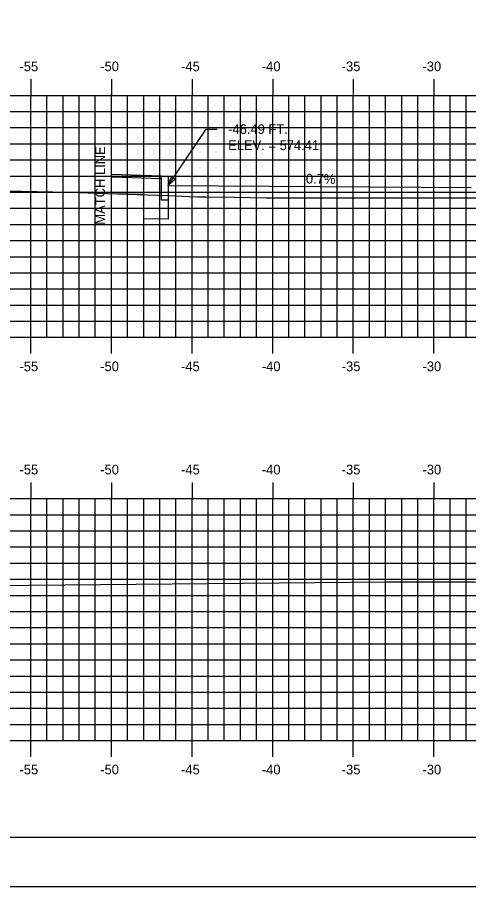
# Model space of a CAD drawing. Extents: x 1048109 to 1048279, y 781630 to 781740.
# Drawn here: x 1048135.9 to 1048163.9, y 781630.1 to 781684 of the extents above; entities that cross this region are included whole.
import ezdxf

# ---------------------------------------------------------------- set-up
doc = ezdxf.new("R2010")
doc.units = 0
for name, color, linetype in [('ANNOTATION', 7, 'Continuous'), ('D_Curb_Type1_Lt', 7, 'Continuous'), ('D_Roadway_Centerline', 7, 'Continuous'), ('D_Roadway_SubGrade', 7, 'Continuous'), ('D_Text_Standard', 7, 'Continuous'), ('Default', 7, 'Continuous'), ('E_ROW_Line', 7, 'Continuous'), ('H_V ANNOTATION', 7, 'Continuous'), ('MAJOR', 7, 'Continuous'), ('MINOR', 7, 'Continuous'), ('S_Roadway_Centerline', 7, 'Continuous'), ('S_Roadway_Edge_Pavement', 7, 'Continuous')]:
    doc.layers.add(name, color=color, linetype=linetype)

msp = doc.modelspace()

# ---------------------------------------------------------------- linework, layer by layer
at = {"layer": 'D_Curb_Type1_Lt'}
msp.add_lwpolyline([(1048145.246, 781674.189), (1048145.246, 781672.689), (1048144.829, 781672.689), (1048144.829, 781674.189)], close=True, dxfattribs=at)
at = {"layer": 'D_Roadway_Centerline'}
msp.add_line((1048145.246, 781673.605), (1048164.033, 781673.476), dxfattribs=at)
at = {"layer": 'D_Roadway_SubGrade'}
for p, q in [((1048144.829, 781674.189), (1048141.733, 781674.292)), ((1048144.829, 781674.022), (1048141.733, 781674.125)), ((1048145.246, 781673.605), (1048145.246, 781671.522)), ((1048145.246, 781671.522), (1048143.746, 781671.552))]:
    msp.add_line(p, q, dxfattribs=at)
msp.add_lwpolyline([(1048143.746, 781671.552), (1048143.746, 781673.053), (1048141.733, 781673.093)], dxfattribs=at)
at = {"layer": 'D_Text_Standard'}
msp.add_lwpolyline([(1048145.246, 781673.605), (1048147.612, 781677.105), (1048148.292, 781677.105)], dxfattribs=at)
msp.add_lwpolyline([(1048145.246, 781673.605), (1048145.451, 781674.169), (1048145.693, 781674.006)], close=True, dxfattribs=at)
at = {"layer": 'Default'}
msp.add_line((1048116.734, 781633.195), (1048276.734, 781633.195), dxfattribs=at)
msp.add_lwpolyline([(1048108.64, 781630.136), (1048278.64, 781630.136), (1048278.64, 781740.136), (1048108.64, 781740.136)], close=True, dxfattribs=at)
at = {"layer": 'E_ROW_Line'}
msp.add_line((1048141.733, 781669.251), (1048141.733, 781679.251), dxfattribs=at)
at = {"layer": 'MAJOR'}
for p, q in [((1048136.733, 781680.197), (1048136.733, 781679.195)), ((1048136.733, 781680.197), (1048136.733, 781679.195)), ((1048141.733, 781680.197), (1048141.733, 781679.195)), ((1048141.733, 781680.197), (1048141.733, 781679.195)), ((1048146.733, 781680.197), (1048146.733, 781679.195)), ((1048146.733, 781680.197), (1048146.733, 781679.195)), ((1048151.733, 781680.197), (1048151.733, 781679.195)), ((1048151.733, 781680.197), (1048151.733, 781679.195)), ((1048156.733, 781680.197), (1048156.733, 781679.195)), ((1048156.733, 781680.197), (1048156.733, 781679.195)), ((1048161.733, 781680.197), (1048161.733, 781679.195)), ((1048161.733, 781680.197), (1048161.733, 781679.195)), ((1048121.733, 781679.195), (1048261.733, 781679.195)), ((1048121.733, 781679.195), (1048261.733, 781679.195)), ((1048121.733, 781679.195), (1048261.733, 781679.195)), ((1048121.733, 781679.195), (1048261.733, 781679.195)), ((1048136.733, 781664.195), (1048136.733, 781679.195)), ((1048136.733, 781664.195), (1048136.733, 781679.195)), ((1048141.733, 781664.195), (1048141.733, 781679.195)), ((1048141.733, 781664.195), (1048141.733, 781679.195)), ((1048146.733, 781664.195), (1048146.733, 781679.195)), ((1048146.733, 781664.195), (1048146.733, 781679.195)), ((1048151.733, 781664.195), (1048151.733, 781679.195)), ((1048151.733, 781664.195), (1048151.733, 781679.195)), ((1048156.733, 781664.195), (1048156.733, 781679.195)), ((1048156.733, 781664.195), (1048156.733, 781679.195)), ((1048161.733, 781664.195), (1048161.733, 781679.195)), ((1048161.733, 781664.195), (1048161.733, 781679.195)), ((1048121.733, 781674.195), (1048261.733, 781674.195)), ((1048121.733, 781674.195), (1048261.733, 781674.195)), ((1048121.733, 781669.195), (1048261.733, 781669.195)), ((1048121.733, 781669.195), (1048261.733, 781669.195)), ((1048121.733, 781664.195), (1048261.733, 781664.195)), ((1048121.733, 781664.195), (1048261.733, 781664.195)), ((1048121.733, 781664.195), (1048261.733, 781664.195)), ((1048121.733, 781664.195), (1048261.733, 781664.195)), ((1048136.733, 781663.193), (1048136.733, 781664.195)), ((1048136.733, 781663.193), (1048136.733, 781664.195)), ((1048141.733, 781663.193), (1048141.733, 781664.195)), ((1048141.733, 781663.193), (1048141.733, 781664.195)), ((1048146.733, 781663.193), (1048146.733, 781664.195)), ((1048146.733, 781663.193), (1048146.733, 781664.195)), ((1048151.733, 781663.193), (1048151.733, 781664.195)), ((1048151.733, 781663.193), (1048151.733, 781664.195)), ((1048156.733, 781663.193), (1048156.733, 781664.195)), ((1048156.733, 781663.193), (1048156.733, 781664.195)), ((1048161.733, 781663.193), (1048161.733, 781664.195)), ((1048161.733, 781663.193), (1048161.733, 781664.195)), ((1048136.733, 781655.197), (1048136.733, 781654.195)), ((1048136.733, 781655.197), (1048136.733, 781654.195)), ((1048141.733, 781655.197), (1048141.733, 781654.195)), ((1048141.733, 781655.197), (1048141.733, 781654.195)), ((1048146.733, 781655.197), (1048146.733, 781654.195)), ((1048146.733, 781655.197), (1048146.733, 781654.195)), ((1048151.733, 781655.197), (1048151.733, 781654.195)), ((1048151.733, 781655.197), (1048151.733, 781654.195)), ((1048156.733, 781655.197), (1048156.733, 781654.195)), ((1048156.733, 781655.197), (1048156.733, 781654.195)), ((1048161.733, 781655.197), (1048161.733, 781654.195)), ((1048161.733, 781655.197), (1048161.733, 781654.195)), ((1048121.733, 781654.195), (1048261.733, 781654.195)), ((1048121.733, 781654.195), (1048261.733, 781654.195)), ((1048121.733, 781654.195), (1048261.733, 781654.195)), ((1048121.733, 781654.195), (1048261.733, 781654.195)), ((1048136.733, 781639.195), (1048136.733, 781654.195)), ((1048136.733, 781639.195), (1048136.733, 781654.195)), ((1048141.733, 781639.195), (1048141.733, 781654.195)), ((1048141.733, 781639.195), (1048141.733, 781654.195)), ((1048146.733, 781639.195), (1048146.733, 781654.195)), ((1048146.733, 781639.195), (1048146.733, 781654.195)), ((1048151.733, 781639.195), (1048151.733, 781654.195)), ((1048151.733, 781639.195), (1048151.733, 781654.195)), ((1048156.733, 781639.195), (1048156.733, 781654.195)), ((1048156.733, 781639.195), (1048156.733, 781654.195)), ((1048161.733, 781639.195), (1048161.733, 781654.195)), ((1048161.733, 781639.195), (1048161.733, 781654.195)), ((1048121.733, 781649.195), (1048261.733, 781649.195)), ((1048121.733, 781649.195), (1048261.733, 781649.195)), ((1048121.733, 781644.195), (1048261.733, 781644.195)), ((1048121.733, 781644.195), (1048261.733, 781644.195)), ((1048121.733, 781639.195), (1048261.733, 781639.195)), ((1048121.733, 781639.195), (1048261.733, 781639.195)), ((1048121.733, 781639.195), (1048261.733, 781639.195)), ((1048121.733, 781639.195), (1048261.733, 781639.195)), ((1048136.733, 781638.193), (1048136.733, 781639.195)), ((1048136.733, 781638.193), (1048136.733, 781639.195)), ((1048141.733, 781638.193), (1048141.733, 781639.195)), ((1048141.733, 781638.193), (1048141.733, 781639.195)), ((1048146.733, 781638.193), (1048146.733, 781639.195)), ((1048146.733, 781638.193), (1048146.733, 781639.195)), ((1048151.733, 781638.193), (1048151.733, 781639.195)), ((1048151.733, 781638.193), (1048151.733, 781639.195)), ((1048156.733, 781638.193), (1048156.733, 781639.195)), ((1048156.733, 781638.193), (1048156.733, 781639.195)), ((1048161.733, 781638.193), (1048161.733, 781639.195)), ((1048161.733, 781638.193), (1048161.733, 781639.195))]:
    msp.add_line(p, q, dxfattribs=at)
at = {"layer": 'MINOR'}
for p, q in [((1048137.733, 781664.195), (1048137.733, 781679.195)), ((1048137.733, 781664.195), (1048137.733, 781679.195)), ((1048138.733, 781664.195), (1048138.733, 781679.195)), ((1048138.733, 781664.195), (1048138.733, 781679.195)), ((1048139.733, 781664.195), (1048139.733, 781679.195)), ((1048139.733, 781664.195), (1048139.733, 781679.195)), ((1048140.733, 781664.195), (1048140.733, 781679.195)), ((1048140.733, 781664.195), (1048140.733, 781679.195)), ((1048142.733, 781664.195), (1048142.733, 781679.195)), ((1048142.733, 781664.195), (1048142.733, 781679.195)), ((1048143.733, 781664.195), (1048143.733, 781679.195)), ((1048143.733, 781664.195), (1048143.733, 781679.195)), ((1048144.733, 781664.195), (1048144.733, 781679.195)), ((1048144.733, 781664.195), (1048144.733, 781679.195)), ((1048145.733, 781664.195), (1048145.733, 781679.195)), ((1048145.733, 781664.195), (1048145.733, 781679.195)), ((1048147.733, 781664.195), (1048147.733, 781679.195)), ((1048147.733, 781664.195), (1048147.733, 781679.195)), ((1048148.733, 781664.195), (1048148.733, 781679.195)), ((1048148.733, 781664.195), (1048148.733, 781679.195)), ((1048149.733, 781664.195), (1048149.733, 781679.195)), ((1048149.733, 781664.195), (1048149.733, 781679.195)), ((1048150.733, 781664.195), (1048150.733, 781679.195)), ((1048150.733, 781664.195), (1048150.733, 781679.195)), ((1048152.733, 781664.195), (1048152.733, 781679.195)), ((1048152.733, 781664.195), (1048152.733, 781679.195)), ((1048153.733, 781664.195), (1048153.733, 781679.195)), ((1048153.733, 781664.195), (1048153.733, 781679.195)), ((1048154.733, 781664.195), (1048154.733, 781679.195)), ((1048154.733, 781664.195), (1048154.733, 781679.195)), ((1048155.733, 781664.195), (1048155.733, 781679.195)), ((1048155.733, 781664.195), (1048155.733, 781679.195)), ((1048157.733, 781664.195), (1048157.733, 781679.195)), ((1048157.733, 781664.195), (1048157.733, 781679.195)), ((1048158.733, 781664.195), (1048158.733, 781679.195)), ((1048158.733, 781664.195), (1048158.733, 781679.195)), ((1048159.733, 781664.195), (1048159.733, 781679.195)), ((1048159.733, 781664.195), (1048159.733, 781679.195)), ((1048160.733, 781664.195), (1048160.733, 781679.195)), ((1048160.733, 781664.195), (1048160.733, 781679.195)), ((1048162.733, 781664.195), (1048162.733, 781679.195)), ((1048162.733, 781664.195), (1048162.733, 781679.195)), ((1048163.733, 781664.195), (1048163.733, 781679.195)), ((1048163.733, 781664.195), (1048163.733, 781679.195)), ((1048121.733, 781678.195), (1048261.733, 781678.195)), ((1048121.733, 781678.195), (1048261.733, 781678.195)), ((1048121.733, 781677.195), (1048261.733, 781677.195)), ((1048121.733, 781677.195), (1048261.733, 781677.195)), ((1048121.733, 781676.195), (1048261.733, 781676.195)), ((1048121.733, 781676.195), (1048261.733, 781676.195)), ((1048121.733, 781675.195), (1048261.733, 781675.195)), ((1048121.733, 781675.195), (1048261.733, 781675.195)), ((1048121.733, 781673.195), (1048261.733, 781673.195)), ((1048121.733, 781673.195), (1048261.733, 781673.195)), ((1048121.733, 781672.195), (1048261.733, 781672.195)), ((1048121.733, 781672.195), (1048261.733, 781672.195)), ((1048121.733, 781671.195), (1048261.733, 781671.195)), ((1048121.733, 781671.195), (1048261.733, 781671.195)), ((1048121.733, 781670.195), (1048261.733, 781670.195)), ((1048121.733, 781670.195), (1048261.733, 781670.195)), ((1048121.733, 781668.195), (1048261.733, 781668.195)), ((1048121.733, 781668.195), (1048261.733, 781668.195)), ((1048121.733, 781667.195), (1048261.733, 781667.195)), ((1048121.733, 781667.195), (1048261.733, 781667.195)), ((1048121.733, 781666.195), (1048261.733, 781666.195)), ((1048121.733, 781666.195), (1048261.733, 781666.195)), ((1048121.733, 781665.195), (1048261.733, 781665.195)), ((1048121.733, 781665.195), (1048261.733, 781665.195)), ((1048137.733, 781639.195), (1048137.733, 781654.195)), ((1048137.733, 781639.195), (1048137.733, 781654.195)), ((1048138.733, 781639.195), (1048138.733, 781654.195)), ((1048138.733, 781639.195), (1048138.733, 781654.195)), ((1048139.733, 781639.195), (1048139.733, 781654.195)), ((1048139.733, 781639.195), (1048139.733, 781654.195)), ((1048140.733, 781639.195), (1048140.733, 781654.195)), ((1048140.733, 781639.195), (1048140.733, 781654.195)), ((1048142.733, 781639.195), (1048142.733, 781654.195)), ((1048142.733, 781639.195), (1048142.733, 781654.195)), ((1048143.733, 781639.195), (1048143.733, 781654.195)), ((1048143.733, 781639.195), (1048143.733, 781654.195)), ((1048144.733, 781639.195), (1048144.733, 781654.195)), ((1048144.733, 781639.195), (1048144.733, 781654.195)), ((1048145.733, 781639.195), (1048145.733, 781654.195)), ((1048145.733, 781639.195), (1048145.733, 781654.195)), ((1048147.733, 781639.195), (1048147.733, 781654.195)), ((1048147.733, 781639.195), (1048147.733, 781654.195)), ((1048148.733, 781639.195), (1048148.733, 781654.195)), ((1048148.733, 781639.195), (1048148.733, 781654.195)), ((1048149.733, 781639.195), (1048149.733, 781654.195)), ((1048149.733, 781639.195), (1048149.733, 781654.195)), ((1048150.733, 781639.195), (1048150.733, 781654.195)), ((1048150.733, 781639.195), (1048150.733, 781654.195)), ((1048152.733, 781639.195), (1048152.733, 781654.195)), ((1048152.733, 781639.195), (1048152.733, 781654.195)), ((1048153.733, 781639.195), (1048153.733, 781654.195)), ((1048153.733, 781639.195), (1048153.733, 781654.195)), ((1048154.733, 781639.195), (1048154.733, 781654.195)), ((1048154.733, 781639.195), (1048154.733, 781654.195)), ((1048155.733, 781639.195), (1048155.733, 781654.195)), ((1048155.733, 781639.195), (1048155.733, 781654.195)), ((1048157.733, 781639.195), (1048157.733, 781654.195)), ((1048157.733, 781639.195), (1048157.733, 781654.195)), ((1048158.733, 781639.195), (1048158.733, 781654.195)), ((1048158.733, 781639.195), (1048158.733, 781654.195)), ((1048159.733, 781639.195), (1048159.733, 781654.195)), ((1048159.733, 781639.195), (1048159.733, 781654.195)), ((1048160.733, 781639.195), (1048160.733, 781654.195)), ((1048160.733, 781639.195), (1048160.733, 781654.195)), ((1048162.733, 781639.195), (1048162.733, 781654.195)), ((1048162.733, 781639.195), (1048162.733, 781654.195)), ((1048163.733, 781639.195), (1048163.733, 781654.195)), ((1048163.733, 781639.195), (1048163.733, 781654.195)), ((1048121.733, 781653.195), (1048261.733, 781653.195)), ((1048121.733, 781653.195), (1048261.733, 781653.195)), ((1048121.733, 781652.195), (1048261.733, 781652.195)), ((1048121.733, 781652.195), (1048261.733, 781652.195)), ((1048121.733, 781651.195), (1048261.733, 781651.195)), ((1048121.733, 781651.195), (1048261.733, 781651.195)), ((1048121.733, 781650.195), (1048261.733, 781650.195)), ((1048121.733, 781650.195), (1048261.733, 781650.195)), ((1048121.733, 781648.195), (1048261.733, 781648.195)), ((1048121.733, 781648.195), (1048261.733, 781648.195)), ((1048121.733, 781647.195), (1048261.733, 781647.195)), ((1048121.733, 781647.195), (1048261.733, 781647.195)), ((1048121.733, 781646.195), (1048261.733, 781646.195)), ((1048121.733, 781646.195), (1048261.733, 781646.195)), ((1048121.733, 781645.195), (1048261.733, 781645.195)), ((1048121.733, 781645.195), (1048261.733, 781645.195)), ((1048121.733, 781643.195), (1048261.733, 781643.195)), ((1048121.733, 781643.195), (1048261.733, 781643.195)), ((1048121.733, 781642.195), (1048261.733, 781642.195)), ((1048121.733, 781642.195), (1048261.733, 781642.195)), ((1048121.733, 781641.195), (1048261.733, 781641.195)), ((1048121.733, 781641.195), (1048261.733, 781641.195)), ((1048121.733, 781640.195), (1048261.733, 781640.195)), ((1048121.733, 781640.195), (1048261.733, 781640.195))]:
    msp.add_line(p, q, dxfattribs=at)
at = {"layer": 'S_Roadway_Centerline'}
for points in [[(1048121.733, 781673.54), (1048124.021, 781673.514), (1048124.187, 781673.511), (1048124.678, 781673.501), (1048139.044, 781673.199), (1048143.343, 781673.047), (1048145.238, 781672.981), (1048146.562, 781672.932), (1048147.063, 781672.911), (1048147.593, 781672.904), (1048149.373, 781672.876), (1048151.33, 781672.839), (1048151.337, 781672.841), (1048165.263, 781672.839), (1048171.317, 781672.812), (1048173.701, 781672.801), (1048175.841, 781672.789), (1048179.234, 781672.771), (1048191.754, 781672.77), (1048192.331, 781672.75), (1048198.246, 781672.663), (1048213.646, 781672.566), (1048223.979, 781672.514)], [(1048121.733, 781648.883), (1048132.166, 781648.791), (1048158.795, 781649.038), (1048158.833, 781649.037), (1048162.032, 781649.025), (1048164.242, 781649.039), (1048164.257, 781649.038), (1048178.681, 781649.019), (1048190.522, 781649.013), (1048211.019, 781648.954), (1048233.093, 781648.88), (1048259.004, 781648.594), (1048261.733, 781648.51)], [(1048158.829, 781649.037), (1048158.837, 781649.037)]]:
    msp.add_lwpolyline(points, dxfattribs=at)
at = {"layer": 'S_Roadway_Edge_Pavement'}
msp.add_lwpolyline([(1048147.064, 781672.911), (1048147.062, 781672.911)], dxfattribs=at)

# ---------------------------------------------------------------- texts
at = {"layer": 'ANNOTATION'}
msp.add_text('0.7%', height=0.6, rotation=359.2591, dxfattribs=at).set_placement((1048153.788, 781673.733))
at = {"layer": 'D_Text_Standard'}
for s, p in [('-46.49 FT.', (1048148.971, 781676.805)), ('ELEV. = 574.41', (1048148.971, 781675.805))]:
    msp.add_text(s, height=0.6, dxfattribs=at).set_placement(p)
at = {"layer": 'E_ROW_Line'}
msp.add_text('MATCH LINE', height=0.6, rotation=90, dxfattribs=at).set_placement((1048141.333, 781671.179))
at = {"layer": 'H_V ANNOTATION'}
for s, p in [('-55', (1048136.029, 781680.695)), ('-50', (1048141.038, 781680.695)), ('-45', (1048146.051, 781680.695)), ('-40', (1048151.059, 781680.695)), ('-35', (1048156.014, 781680.695)), ('-30', (1048161.022, 781680.695)), ('-55', (1048136.029, 781662.095)), ('-50', (1048141.038, 781662.095)), ('-45', (1048146.051, 781662.095)), ('-40', (1048151.059, 781662.095)), ('-35', (1048156.014, 781662.095)), ('-30', (1048161.022, 781662.095)), ('-55', (1048136.029, 781655.695)), ('-50', (1048141.038, 781655.695)), ('-45', (1048146.051, 781655.695)), ('-40', (1048151.059, 781655.695)), ('-35', (1048156.014, 781655.695)), ('-30', (1048161.022, 781655.695)), ('-55', (1048136.029, 781637.095)), ('-50', (1048141.038, 781637.095)), ('-45', (1048146.051, 781637.095)), ('-40', (1048151.059, 781637.095)), ('-35', (1048156.014, 781637.095)), ('-30', (1048161.022, 781637.095))]:
    msp.add_text(s, height=0.6, dxfattribs=at).set_placement(p)
at = {"layer": 'S_Roadway_Centerline'}
for s, p in [('L', (1048158.824, 781649.03)), ('C', (1048158.827, 781649.037))]:
    msp.add_text(s, height=0.0146, dxfattribs=at).set_placement(p)

doc.saveas('drawing.dxf')
